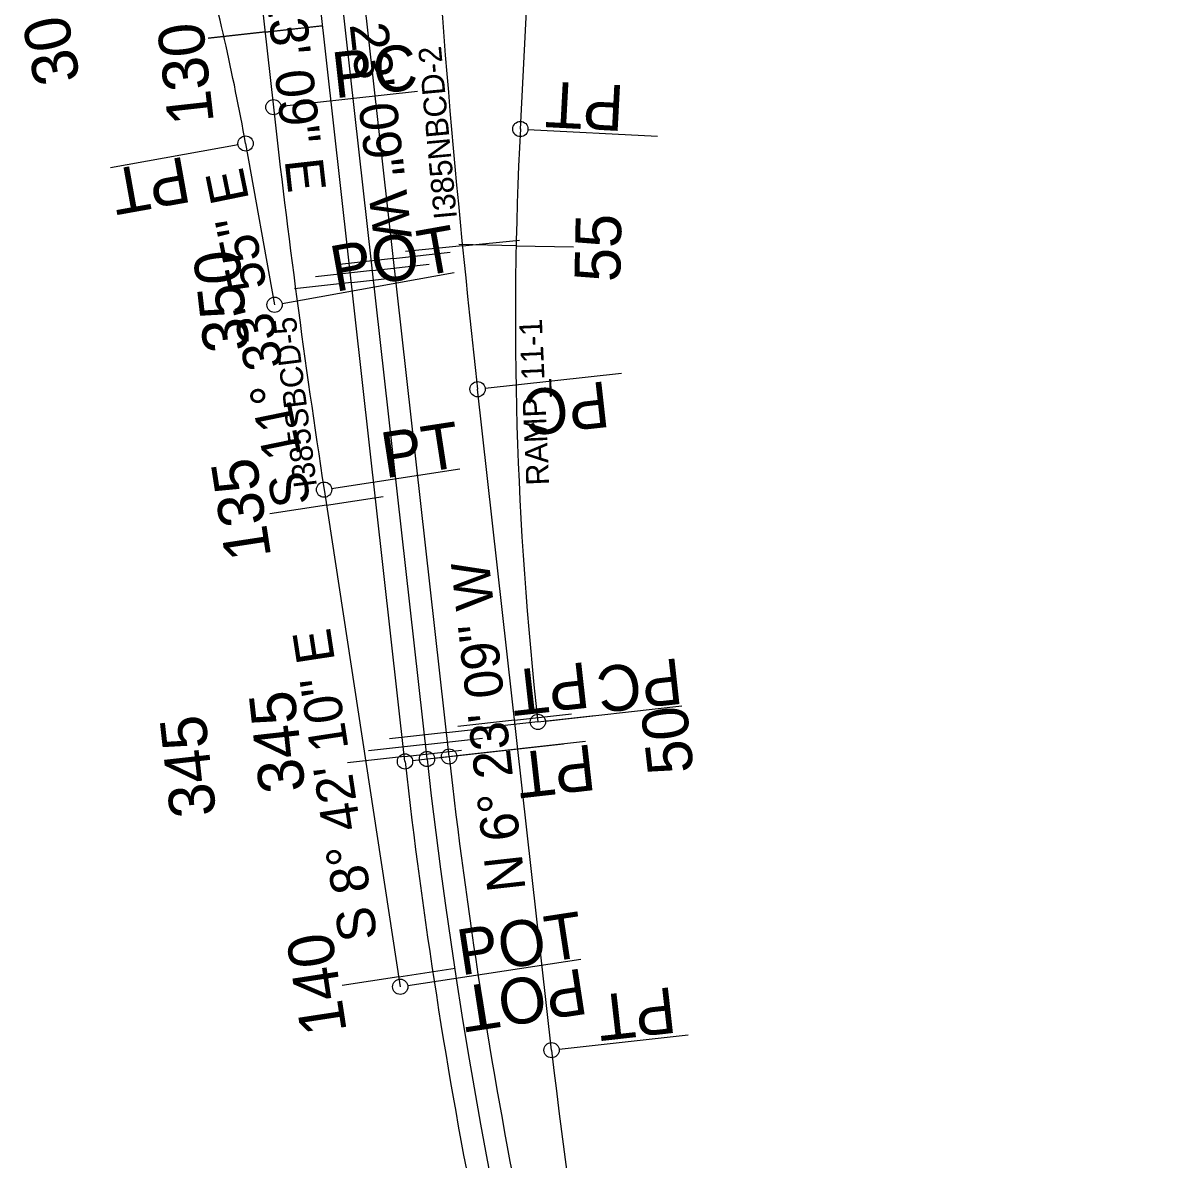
# Model space of a CAD drawing. Extents: x 1603447 to 1622636, y 1083818 to 1103958.
# Drawn here: x 1612087 to 1613297, y 1088478 to 1089669 of the extents above; entities that cross this region are included whole.
import ezdxf

# ---------------------------------------------------------------- set-up
doc = ezdxf.new("R2010")
doc.units = 0
for name, color, linetype in [('Level 1', 7, 'Continuous'), ('RD_HC_SUR_Bearing_TX400', 7, 'Continuous'), ('RD_HC_SUR_CL400', 7, 'Continuous'), ('RD_HC_SUR_PC_PT_400', 7, 'Continuous'), ('RD_HC_SUR_Tic400', 7, 'Continuous'), ('RD_HC_SUR_TX_Sta400', 7, 'Continuous'), ('RD_TX_Misc1', 7, 'Continuous')]:
    doc.layers.add(name, color=color, linetype=linetype)

msp = doc.modelspace()

# ---------------------------------------------------------------- linework, layer by layer
at = {"layer": 'RD_HC_SUR_CL400'}
for p, q in [((1612608.3, 1089558.3), (1612650.6, 1090365.9)), ((1612533.6, 1088900.6), (1612380.9, 1090265.1)), ((1612510.5, 1088898), (1612359.5, 1090247.4)), ((1612487.4, 1088895.4), (1612377.9, 1089874.1)), ((1612331.3, 1089744.5), (1612349.6, 1089581.2)), ((1612320.4, 1089543.1), (1612350.7, 1089374.1)), ((1612641, 1088592.8), (1612563.5, 1089285.6)), ((1612402.6, 1089180.3), (1612482.4, 1088659.3))]:
    msp.add_line(p, q, dxfattribs=at)
for centre, radius, start, end in [((1623992.1, 1090564.7), 11500, 183.27051, 186.3858), ((1609859.7, 1089101.6), 2500, 10.1713, 15.269), ((1622287.5, 1090693.4), 10000, 186.3858, 188.70283), ((1616403.1, 1089359.6), 3800, 177.0015, 186.3858), ((1618204.6, 1089535.2), 5706.3, 186.3858, 196.2335), ((1618204.6, 1089535.2), 5752.8, 186.3858, 196.23352), ((1618204.6, 1089535.2), 5729.6, 186.3858, 211.0768), ((1617212.5, 1089104.4), 4600, 186.3858, 203.4744)]:
    msp.add_arc(centre, radius, start, end, dxfattribs=at)
at = {"layer": 'RD_HC_SUR_PC_PT_400'}
for p, q in [((1612357.5, 1089582.1), (1612500.4, 1089598)), ((1612616.3, 1089557.9), (1612751.9, 1089550.8)), ((1612312.5, 1089541.6), (1612178.8, 1089517.7)), ((1612358.6, 1089375.5), (1612539.1, 1089407.9)), ((1612571.4, 1089286.5), (1612714.3, 1089302.5)), ((1612410.5, 1089181.5), (1612544.8, 1089202.1)), ((1612634.6, 1088937.8), (1612777.5, 1088953.8)), ((1612518.5, 1088898.9), (1612653.5, 1088914)), ((1612541.6, 1088901.5), (1612676.6, 1088916.6)), ((1612495.4, 1088896.3), (1612630.4, 1088911.4)), ((1612490.3, 1088660.5), (1612671.6, 1088688.3)), ((1612490.3, 1088660.5), (1612671.6, 1088688.3)), ((1612649, 1088593.7), (1612784, 1088608.8))]:
    msp.add_line(p, q, dxfattribs=at)
for centre in [(1612349.6, 1089581.2), (1612608.3, 1089558.3), (1612320.4, 1089543.1), (1612350.7, 1089374.1), (1612563.5, 1089285.6), (1612402.6, 1089180.3), (1612626.7, 1088936.9), (1612487.4, 1088895.4), (1612510.5, 1088898), (1612533.6, 1088900.6), (1612482.4, 1088659.3), (1612641, 1088592.8)]:
    msp.add_circle(centre, 8, dxfattribs=at)
at = {"layer": 'RD_HC_SUR_Tic400'}
for p, q in [((1612340.8, 1089659.8), (1612400.4, 1089666.5)), ((1612341.2, 1089660.1), (1612400.8, 1089666.8)), ((1612340.8, 1089659.8), (1612281.1, 1089653.1)), ((1612341.2, 1089660.1), (1612281.6, 1089653.5)), ((1612529.8, 1089635), (1612529.8, 1089635)), ((1612612.4, 1089635.8), (1612612.4, 1089635.8)), ((1612453, 1089621.3), (1612453, 1089621.3)), ((1612431, 1089608.8), (1612431, 1089608.8)), ((1612409, 1089596.2), (1612409, 1089596.2)), ((1612312.1, 1089587.2), (1612312.1, 1089587.2)), ((1612351.9, 1089560.4), (1612351.9, 1089560.4)), ((1612352.3, 1089560.8), (1612352.3, 1089560.8)), ((1612538.3, 1089535.3), (1612538.3, 1089535.3)), ((1612607.2, 1089536), (1612607.2, 1089536)), ((1612464.1, 1089521.9), (1612464.1, 1089521.9)), ((1612442.1, 1089509.4), (1612442.1, 1089509.4)), ((1612420.1, 1089496.9), (1612420.1, 1089496.9)), ((1612330.1, 1089488.8), (1612330.1, 1089488.8)), ((1612363.5, 1089461.4), (1612363.5, 1089461.4)), ((1612363.7, 1089461.1), (1612363.7, 1089461.1)), ((1612547.7, 1089435.8), (1612488, 1089429.9)), ((1612603.9, 1089436), (1612543.9, 1089437.2)), ((1612547.7, 1089435.8), (1612607.4, 1089441.7)), ((1612603.9, 1089436), (1612663.9, 1089434.8)), ((1612475.2, 1089422.6), (1612415.6, 1089415.9)), ((1612475.2, 1089422.6), (1612534.8, 1089429.2)), ((1612453.2, 1089410), (1612393.6, 1089403.3)), ((1612453.2, 1089410), (1612512.9, 1089416.7)), ((1612431.2, 1089397.5), (1612371.6, 1089390.8)), ((1612431.2, 1089397.5), (1612490.9, 1089404.1)), ((1612347.8, 1089390.4), (1612347.8, 1089390.4)), ((1612375.8, 1089362.2), (1612375.8, 1089362.2)), ((1612376.5, 1089361.9), (1612376.5, 1089361.9)), ((1612557.9, 1089336.3), (1612557.9, 1089336.3)), ((1612603.2, 1089336), (1612603.2, 1089336)), ((1612486.3, 1089323.2), (1612486.3, 1089323.2)), ((1612464.4, 1089310.6), (1612464.4, 1089310.6)), ((1612442.4, 1089298.1), (1612442.4, 1089298.1)), ((1612390, 1089263.2), (1612390, 1089263.2)), ((1612390.3, 1089262.9), (1612390.3, 1089262.9)), ((1612605.1, 1089236), (1612605.1, 1089236)), ((1612497.5, 1089223.8), (1612497.5, 1089223.8)), ((1612475.5, 1089211.3), (1612475.5, 1089211.3)), ((1612453.5, 1089198.7), (1612453.5, 1089198.7)), ((1612405.1, 1089164), (1612464.4, 1089173.1)), ((1612405.1, 1089164), (1612345.8, 1089154.9)), ((1612580.1, 1089137.5), (1612580.1, 1089137.5)), ((1612609.7, 1089136.2), (1612609.7, 1089136.2)), ((1612508.6, 1089124.4), (1612508.6, 1089124.4)), ((1612486.6, 1089111.9), (1612486.6, 1089111.9)), ((1612464.6, 1089099.3), (1612464.6, 1089099.3)), ((1612420.2, 1089065.5), (1612420.2, 1089065.5)), ((1612420.3, 1089065.2), (1612420.3, 1089065.2)), ((1612616.9, 1089036.4), (1612616.9, 1089036.4)), ((1612519.7, 1089025), (1612519.7, 1089025)), ((1612497.7, 1089012.5), (1612497.7, 1089012.5)), ((1612475.7, 1089000), (1612475.7, 1089000)), ((1612435.4, 1088966.6), (1612435.4, 1088966.6)), ((1612435.4, 1088966.3), (1612435.4, 1088966.3)), ((1612602.3, 1088938.8), (1612542.7, 1088932.1)), ((1612626.7, 1088936.9), (1612567, 1088930.2)), ((1612602.3, 1088938.8), (1612661.9, 1088945.4)), ((1612626.7, 1088936.9), (1612686.3, 1088943.6)), ((1612530.8, 1088925.7), (1612471.2, 1088919)), ((1612530.8, 1088925.7), (1612590.5, 1088932.3)), ((1612508.8, 1088913.1), (1612449.2, 1088906.4)), ((1612508.8, 1088913.1), (1612568.5, 1088919.8)), ((1612486.9, 1088900.6), (1612427.2, 1088893.9)), ((1612486.9, 1088900.6), (1612546.5, 1088907.2)), ((1612450.5, 1088867.8), (1612450.5, 1088867.8)), ((1612450.5, 1088867.5), (1612450.5, 1088867.5)), ((1612542.4, 1088826.3), (1612542.4, 1088826.3)), ((1612520.6, 1088813.8), (1612520.6, 1088813.8)), ((1612498.7, 1088801.3), (1612498.7, 1088801.3)), ((1612465.6, 1088768.9), (1612465.6, 1088768.9)), ((1612465.7, 1088768.6), (1612465.7, 1088768.6)), ((1612555.7, 1088727.2), (1612555.7, 1088727.2)), ((1612534, 1088714.7), (1612534, 1088714.7)), ((1612512.4, 1088702.2), (1612512.4, 1088702.2)), ((1612480.8, 1088669.8), (1612421.5, 1088660.7)), ((1612480.8, 1088669.8), (1612540.1, 1088678.8)), ((1612635.7, 1088640.6), (1612635.7, 1088640.6)), ((1612570.8, 1088628.4), (1612570.8, 1088628.4)), ((1612549.2, 1088615.9), (1612549.2, 1088615.9)), ((1612527.7, 1088603.4), (1612527.7, 1088603.4)), ((1612647.1, 1088541.3), (1612647.1, 1088541.3)), ((1612587.5, 1088529.8), (1612587.5, 1088529.8)), ((1612566.1, 1088517.3), (1612566.1, 1088517.3)), ((1612544.8, 1088504.9), (1612544.8, 1088504.9))]:
    msp.add_line(p, q, dxfattribs=at)

# ---------------------------------------------------------------- texts
at = {"layer": 'Level 1'}
for s, rotation, p in [('55', 88.8469, (1612712.9, 1089397.6)), ('135', 98.7028, (1612347.3, 1089110.1)), ('345', 96.3858, (1612383.1, 1088865.2)), ('345', 96.3858, (1612289.7, 1088839.5))]:
    msp.add_text(s, height=48, rotation=rotation, dxfattribs=at).set_placement(p)
at = {"layer": 'RD_HC_SUR_Bearing_TX400'}
for s, rotation, p in [('S 6%%d 23\' 09" E', 276.3858, (1612328.5, 1089818.3)), ('N 6%%d 23\' 09" W', 276.3858, (1612416.1, 1089786.6)), ('S 11%%d 33\' 55" E', 101.5652, (1612389.2, 1089166.8)), ('N 6%%d 23\' 09" W', 96.3858, (1612613.9, 1088761.1)), ('S 8%%d 42\' 10" E', 98.7028, (1612458.7, 1088710.2))]:
    msp.add_text(s, height=40, rotation=rotation, dxfattribs=at).set_placement(p)
at = {"layer": 'RD_HC_SUR_PC_PT_400'}
for s, rotation, p in [('PC', 6.3858, (1612413.9, 1089590.4)), ('PT', 177.0015, (1612718, 1089604)), ('PT', 190.1713, (1612256.8, 1089529.6)), ('POT', 10.1713, (1612414.3, 1089387.5)), ('PC', 186.3858, (1612698.3, 1089294.1)), ('PT', 8.7028, (1612466.6, 1089192.1)), ('PT', 186.3858, (1612677.3, 1088999.8)), ('PC', 186.3858, (1612774.9, 1089003.9)), ('PT', 186.3858, (1612683.7, 1088913.5)), ('POT', 8.7028, (1612546.3, 1088671.1)), ('POT', 188.7028, (1612673.5, 1088678.8)), ('PT', 186.3858, (1612768.1, 1088659.1))]:
    msp.add_text(s, height=48, rotation=rotation, dxfattribs=at).set_placement(p)
at = {"layer": 'RD_HC_SUR_TX_Sta400'}
for s, rotation, p in [('30', 101.8655, (1612147.6, 1089610.3)), ('130', 96.3858, (1612287.2, 1089565.5)), ('350', 96.3858, (1612324.9, 1089327.1)), ('50', 96.3858, (1612790.1, 1088884.7)), ('140', 98.7028, (1612426.5, 1088612.5))]:
    msp.add_text(s, height=48, rotation=rotation, dxfattribs=at).set_placement(p)
at = {"layer": 'RD_TX_Misc1'}
for s, rotation, p in [('I385NBCD-2', 95.3167, (1612541.9, 1089464.9)), ('I385SBCD-5', 97.1252, (1612395.2, 1089183.8)), ('RAMP_11-1', 92.5495, (1612638.6, 1089185.2))]:
    msp.add_text(s, height=24, rotation=rotation, dxfattribs=at).set_placement(p)

doc.saveas('drawing.dxf')
